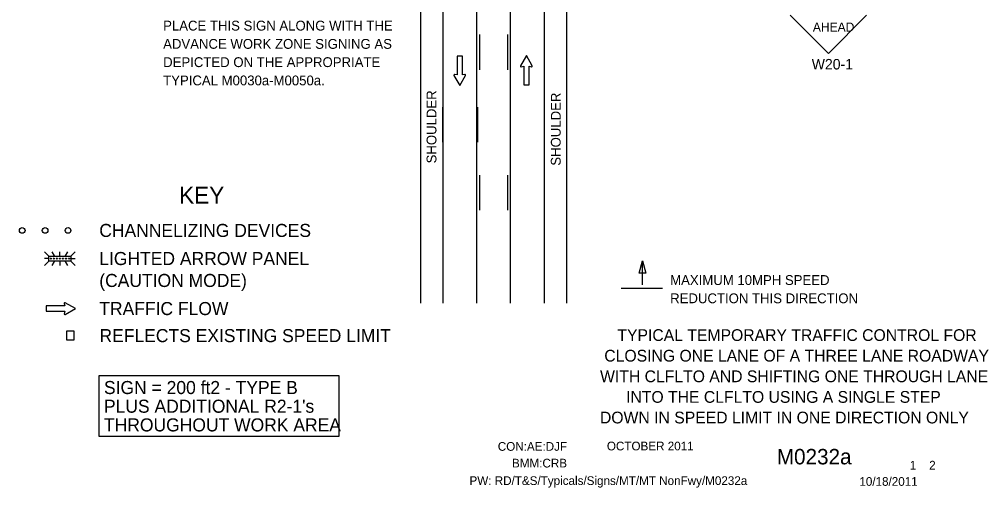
# Model space of a CAD drawing. Extents: x 16750 to 18296, y 5932 to 6919.
# Drawn here: x 16750 to 17440, y 5932 to 6265 of the extents above; entities that cross this region are included whole.
import ezdxf

# ---------------------------------------------------------------- set-up
doc = ezdxf.new("R2010")
doc.units = 0
for name, color, linetype in [('BORDER', 7, 'Continuous'), ('BORDER_SIGNAL_WO', 7, 'Continuous'), ('MT_SCRATCH_LEVEL_A', 7, 'Continuous'), ('MT_SCRATCH_LEVEL_E', 7, 'Continuous'), ('PAVT_EDGE_EX', 7, 'Continuous'), ('TRAFFIC_SIGNS_PR', 7, 'Continuous'), ('TYPICAL_TEXT_DIMEN_EX', 7, 'Continuous'), ('TYPICAL_TEXT_DIMEN_PR', 7, 'Continuous')]:
    doc.layers.add(name, color=color, linetype=linetype)

msp = doc.modelspace()

# ---------------------------------------------------------------- linework, layer by layer
at = {"layer": 'BORDER'}
for p, q in [((17051.59, 6917.57), (17051.59, 6063.18)), ((17123.59, 6917.57), (17123.59, 6063.18))]:
    msp.add_line(p, q, dxfattribs=at)
at = {"layer": 'MT_SCRATCH_LEVEL_A'}
for p, q in [((17075.59, 6917.57), (17075.59, 6063.18)), ((17099.59, 6464.33), (17099.59, 6063.18))]:
    msp.add_line(p, q, dxfattribs=at)
for points in [[(17077.59, 6254.22), (17077.59, 6229.22)], [(17097.59, 6254.22), (17097.59, 6229.22)], [(17077.59, 6154.22), (17077.59, 6129.22)], [(17097.59, 6154.22), (17097.59, 6129.22)]]:
    msp.add_lwpolyline(points, dxfattribs=at)
at = {"layer": 'MT_SCRATCH_LEVEL_E'}
for p, q in [((17065.51, 6238.87), (17061.77, 6238.87)), ((17061.77, 6238.87), (17061.77, 6225.61)), ((17065.51, 6238.87), (17061.77, 6238.87)), ((17061.77, 6238.87), (17061.77, 6225.61)), ((17065.51, 6225.61), (17065.51, 6238.87)), ((17065.51, 6225.61), (17065.51, 6238.87)), ((17111.03, 6239.33), (17106.91, 6232.09)), ((17111.03, 6239.33), (17106.91, 6232.09)), ((17115.17, 6232.09), (17111.03, 6239.33)), ((17115.17, 6232.09), (17111.03, 6239.33)), ((17107.4, 6231.4), (17109.17, 6231.72)), ((17107.4, 6231.4), (17109.17, 6231.72)), ((17109.17, 6231.72), (17109.17, 6218.46)), ((17109.17, 6231.72), (17109.17, 6218.46)), ((17112.92, 6218.46), (17112.92, 6231.72)), ((17112.92, 6231.72), (17114.69, 6231.4)), ((17112.92, 6218.46), (17112.92, 6231.72)), ((17112.92, 6231.72), (17114.69, 6231.4)), ((17059.51, 6225.24), (17063.66, 6218)), ((17059.51, 6225.24), (17063.66, 6218)), ((17061.77, 6225.61), (17059.99, 6225.93)), ((17061.77, 6225.61), (17059.99, 6225.93)), ((17063.66, 6218), (17067.77, 6225.24)), ((17063.66, 6218), (17067.77, 6225.24)), ((17067.29, 6225.93), (17065.51, 6225.61)), ((17067.29, 6225.93), (17065.51, 6225.61)), ((17109.17, 6218.46), (17112.92, 6218.46)), ((17109.17, 6218.46), (17112.92, 6218.46)), ((16782.58, 6061.14), (16769.32, 6061.14)), ((16769.32, 6061.14), (16769.32, 6057.39)), ((16782.58, 6061.14), (16769.32, 6061.14)), ((16769.32, 6061.14), (16769.32, 6057.39)), ((16782.26, 6062.91), (16782.58, 6061.14)), ((16782.26, 6062.91), (16782.58, 6061.14)), ((16790.19, 6059.28), (16782.95, 6063.39)), ((16790.19, 6059.28), (16782.95, 6063.39)), ((16769.32, 6057.39), (16782.58, 6057.39)), ((16769.32, 6057.39), (16782.58, 6057.39)), ((16782.58, 6057.39), (16782.26, 6055.62)), ((16782.58, 6057.39), (16782.26, 6055.62)), ((16782.95, 6055.14), (16790.19, 6059.28)), ((16782.95, 6055.14), (16790.19, 6059.28))]:
    msp.add_line(p, q, dxfattribs=at)
for centre, start, end in [((17107.32, 6231.86), 150.42484, 279.96381), ((17107.32, 6231.86), 150.42484, 279.96381), ((17114.76, 6231.86), 260.03619, 29.77312), ((17114.76, 6231.86), 260.03619, 29.77312), ((17059.92, 6225.47), 80.03619, 209.77312), ((17059.92, 6225.47), 80.03619, 209.77312), ((17067.37, 6225.47), 330.42484, 99.96381), ((17067.37, 6225.47), 330.42484, 99.96381), ((16782.72, 6062.99), 60.42484, 189.96381), ((16782.72, 6062.99), 60.42484, 189.96381), ((16782.72, 6055.55), 170.03619, 299.77312), ((16782.72, 6055.55), 170.03619, 299.77312)]:
    msp.add_arc(centre, 0.463, start, end, dxfattribs=at)
at = {"layer": 'PAVT_EDGE_EX'}
for p, q in [((17035.59, 6917.57), (17035.59, 6063.18)), ((17139.59, 6917.57), (17139.59, 6063.18))]:
    msp.add_line(p, q, dxfattribs=at)
for points in [[(17051.59, 6177.68), (17051.59, 6202.68)], [(17076.59, 6177.68), (17076.59, 6202.68)]]:
    msp.add_lwpolyline(points, dxfattribs=at)
at = {"layer": 'TRAFFIC_SIGNS_PR'}
for p, q in [((17298.7, 6268.1), (17325.89, 6240.91)), ((17325.89, 6240.91), (17353.07, 6268.1)), ((16768.19, 6099.73), (16771, 6096.92)), ((16775.27, 6096.92), (16773.65, 6099.74)), ((16779.09, 6096.92), (16779.09, 6099.74)), ((16783.22, 6096.92), (16784.85, 6099.74)), ((16787.17, 6096.92), (16790, 6099.74)), ((16771, 6094.88), (16768.19, 6094.88)), ((16768.19, 6090.03), (16771, 6092.85)), ((16772.64, 6094.88), (16772.64, 6094.88)), ((16773.62, 6090.03), (16775.25, 6092.85)), ((16774.82, 6094.88), (16774.82, 6094.88)), ((16776.99, 6094.88), (16776.99, 6094.88)), ((16779.09, 6092.85), (16779.09, 6090.03)), ((16779.16, 6094.88), (16779.16, 6094.88)), ((16781.34, 6094.88), (16781.34, 6094.88)), ((16784.88, 6090.03), (16783.25, 6092.85)), ((16783.51, 6094.88), (16783.51, 6094.88)), ((16785.68, 6094.88), (16785.68, 6094.88)), ((16787.17, 6094.88), (16790, 6094.88)), ((16787.17, 6092.85), (16790, 6090.03))]:
    msp.add_line(p, q, dxfattribs=at)
for points in [[(16786.94, 6093.08), (16771.24, 6093.08), (16771.24, 6096.68), (16786.94, 6096.68)], [(16783.75, 6036.93), (16789.35, 6036.93), (16789.35, 6043.1), (16783.75, 6043.1)]]:
    msp.add_lwpolyline(points, close=True, dxfattribs=at)
for centre, radius in [((16752.34, 6114.88), 2), ((16768.64, 6114.88), 2), ((16784.94, 6114.88), 2), ((16772.66, 6094.88), 0.379), ((16774.82, 6094.88), 0.379), ((16776.99, 6094.88), 0.379), ((16779.16, 6094.88), 0.379), ((16781.34, 6094.88), 0.379), ((16783.51, 6094.88), 0.379), ((16785.68, 6094.88), 0.379)]:
    msp.add_circle(centre, radius, dxfattribs=at)
at = {"layer": 'TYPICAL_TEXT_DIMEN_EX'}
msp.add_lwpolyline([(16807.18, 6011.55), (16977.58, 6011.55), (16977.58, 5968.18), (16807.18, 5968.18)], close=True, dxfattribs=at)
at = {"layer": 'TYPICAL_TEXT_DIMEN_PR'}
for p, q in [((17191.27, 6084.48), (17193.63, 6093.27)), ((17193.63, 6076.15), (17193.63, 6093.27)), ((17193.63, 6093.27), (17195.98, 6084.48)), ((17193.63, 6084.48), (17191.27, 6084.48)), ((17195.98, 6084.48), (17193.63, 6084.48)), ((17207.8, 6073.65), (17178.36, 6073.65))]:
    msp.add_line(p, q, dxfattribs=at)

# ---------------------------------------------------------------- texts
at = {"layer": 'BORDER_SIGNAL_WO'}
for s, height, p in [('TYPICAL TEMPORARY TRAFFIC CONTROL FOR', 8.37, (17175.78, 6036.21)), ('CLOSING ONE LANE OF A THREE LANE ROADWAY', 8.37, (17166.47, 6021.54)), ('WITH CLFLTO AND SHIFTING ONE THROUGH LANE', 8.37, (17163.45, 6006.87)), ('INTO THE CLFLTO USING A SINGLE STEP', 8.37, (17181.95, 5992.2)), ('DOWN IN SPEED LIMIT IN ONE DIRECTION ONLY', 8.37, (17163.38, 5977.53)), ('    OCTOBER 2011    ', 6.2, (17159.08, 5958.34)), ('CON:AE:DJF  ', 6.2, (17090.69, 5958.06)), ('    M0232a   ', 11, (17272.86, 5948.38)), ('BMM:CRB   ', 6.2, (17100.81, 5946.17)), (' 1    2 ', 6.2, (17381.45, 5944.7)), ('PW: RD/T&S/Typicals/Signs/MT/MT NonFwy/M0232a  ', 6.2, (17070.55, 5933.71)), ('10/18/2011    ', 6.2, (17347.93, 5933.13))]:
    msp.add_text(s, height=height, dxfattribs=at).set_placement(p)
at = {"layer": 'TRAFFIC_SIGNS_PR'}
for s, height, p in [('PLACE THIS SIGN ALONG WITH THE', 7, (16852.62, 6257.14)), ('AHEAD', 6.408, (17314.83, 6256.42)), ('ADVANCE WORK ZONE SIGNING AS', 7, (16852.62, 6244.14)), ('DEPICTED ON THE APPROPRIATE', 7, (16852.62, 6231.14)), ('W20-1', 7.449, (17314.04, 6229.46)), ('TYPICAL M0030a-M0050a.', 7, (16852.62, 6218.14))]:
    msp.add_text(s, height=height, dxfattribs=at).set_placement(p)
at = {"layer": 'TYPICAL_TEXT_DIMEN_EX'}
for p in [(17047.04, 6162.59), (17135.45, 6160.96)]:
    msp.add_text('SHOULDER', height=7, rotation=90, dxfattribs=at).set_placement(p)
for s, height, p in [('KEY', 12, (16863.98, 6133.99)), ('CHANNELIZING DEVICES', 9.3, (16807.18, 6110.23)), ('LIGHTED ARROW PANEL', 9.3, (16807.18, 6090.23)), ('(CAUTION MODE)', 9.3, (16807.18, 6074.63)), ('TRAFFIC FLOW', 9.3, (16807.18, 6054.63)), ('REFLECTS EXISTING SPEED LIMIT', 9.3, (16807.33, 6035.37)), ('SIGN = 200 ft2 - TYPE B', 9.3, (16810.52, 5998.43)), ("PLUS ADDITIONAL R2-1's", 9.3, (16810.52, 5985.13)), ('THROUGHOUT WORK AREA', 9.3, (16810.52, 5971.83))]:
    msp.add_text(s, height=height, dxfattribs=at).set_placement(p)
at = {"layer": 'TYPICAL_TEXT_DIMEN_PR'}
for s, p in [('MAXIMUM 10MPH SPEED', (17213.32, 6076.07)), ('REDUCTION THIS DIRECTION', (17213.32, 6063.07))]:
    msp.add_text(s, height=7, dxfattribs=at).set_placement(p)

doc.saveas('drawing.dxf')
